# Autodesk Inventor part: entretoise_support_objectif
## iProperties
Created: 2011-01
Part Number: entretoise_support_objectif
Document SubType Name: Modeling
Designer: eric
Density: 1 g/cm^3
Mass: 0.212694 g
Surface Area: 5.01492 cm^2
Volume: 0.212694 cm^3
Author: eric
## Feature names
1. Base1
